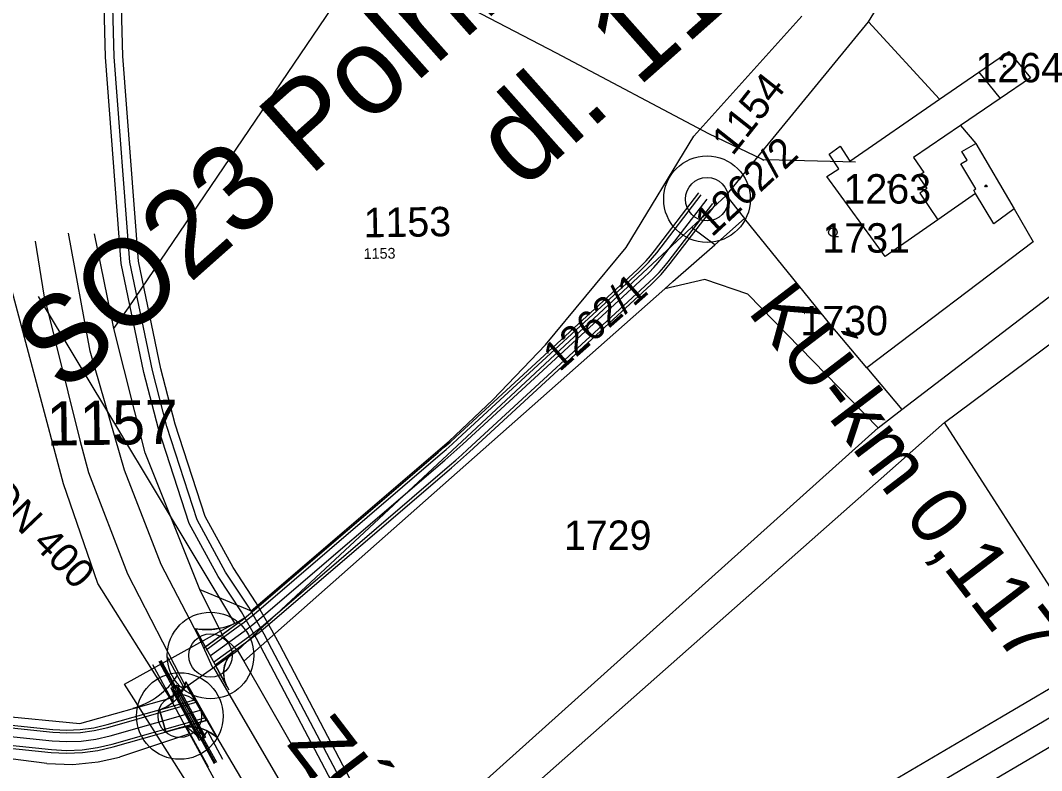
# Model space of a CAD drawing. Extents: x -510185 to -506993, y -1126306 to -1123642.
# Drawn here: x -508329.2 to -508152.3, y -1123958.7 to -1123828.7 of the extents above; entities that cross this region are included whole.
import ezdxf

# ---------------------------------------------------------------- set-up
doc = ezdxf.new("R2010")
doc.units = 0
for name, color, linetype in [('Net4gas', 7, 'Continuous'), ('návrh', 7, 'Continuous'), ('parcelni hranice', 7, 'Continuous'), ('popis cesty', 7, 'Continuous'), ('telefonica', 7, 'Continuous'), ('u_cesta23', 7, 'Continuous'), ('u_cesta45', 7, 'Continuous'), ('u_cesta50', 7, 'Continuous'), ('u_net4gas', 7, 'Continuous'), ('u_osa23', 7, 'Continuous'), ('u_osa50', 7, 'Continuous'), ('u_propustky', 7, 'Continuous'), ('u_Telefonica', 7, 'Continuous'), ('u_VaK', 7, 'Continuous'), ('u_ČEZ nadzemní nn', 7, 'Continuous'), ('u_ČEZ podzemní NN', 7, 'Continuous'), ('ˇ1', 7, 'Continuous'), ('ˇ2', 7, 'Continuous'), ('ˇ3', 7, 'Continuous'), ('ˇ4', 7, 'Continuous'), ('ˇ5', 7, 'Continuous')]:
    doc.layers.add(name, color=color, linetype=linetype)

msp = doc.modelspace()

# ---------------------------------------------------------------- linework, layer by layer
at = {"layer": 'Net4gas'}
for points in [[(-508209.34, -1123978.83), (-508159.28, -1123949.34), (-508132.58, -1123933.61), (-508126.96, -1123929.15), (-508083.48, -1123890.01), (-508045.36, -1123855.26), (-508012.03, -1123825.37), (-507981.75, -1123798.69), (-507943.8, -1123765.47), (-507913.54, -1123739.15), (-507890, -1123718.31)], [(-508198.87, -1123982.75), (-508154.86, -1123956.84), (-508127.64, -1123940.8), (-508121.34, -1123935.8), (-508077.64, -1123896.45), (-508039.53, -1123861.72), (-508006.25, -1123831.88), (-507976.01, -1123805.23), (-507938.08, -1123772.03), (-507907.8, -1123745.69), (-507890, -1123729.93)]]:
    msp.add_lwpolyline(points, dxfattribs=at)
at = {"layer": 'návrh'}
for centre, radius in [((-508210.29, -1123859.63), 7.5), ((-508210.29, -1123859.63), 3.75), ((-508296.29, -1123938.72), 7.5), ((-508296.29, -1123938.72), 3.75), ((-508301.61, -1123949.2), 7.5), ((-508301.61, -1123949.2), 3.75)]:
    msp.add_circle(centre, radius, dxfattribs=at)
at = {"layer": 'parcelni hranice'}
for p, q in [((-508182.33, -1123828.91), (-508153.43, -1123781.85)), ((-508207, -1123859.02), (-508182.33, -1123828.91)), ((-508182.33, -1123828.91), (-508170.02, -1123842.31)), ((-508163.21, -1123837.61), (-508158.04, -1123834.04)), ((-508158.04, -1123834.04), (-508154.26, -1123838.61)), ((-508170.02, -1123842.31), (-508163.21, -1123837.61)), ((-508163.21, -1123837.61), (-508159.52, -1123842.19)), ((-508154.26, -1123838.61), (-508159.52, -1123842.19)), ((-508185.53, -1123853.02), (-508170.02, -1123842.31)), ((-508159.52, -1123842.19), (-508166.38, -1123846.86)), ((-508166.38, -1123846.86), (-508163.75, -1123849.97)), ((-508189.11, -1123851.83), (-508187.21, -1123850.47)), ((-508187.21, -1123850.47), (-508185.53, -1123853.02)), ((-508163.75, -1123849.97), (-508157.1, -1123861.32)), ((-508187.46, -1123854.37), (-508189.11, -1123851.83)), ((-508189.52, -1123855.7), (-508187.46, -1123854.37)), ((-508179.44, -1123869.55), (-508189.52, -1123855.7)), ((-508212.95, -1123864.56), (-508207, -1123859.02)), ((-508207, -1123859.02), (-508206.25, -1123859.95)), ((-508206.25, -1123859.95), (-508203.81, -1123862.97)), ((-508163.76, -1123858.64), (-508170.3, -1123863.2)), ((-508160.63, -1123863.89), (-508163.76, -1123858.64)), ((-508176.54, -1123896.06), (-508130.51, -1123860.84)), ((-508157.1, -1123861.32), (-508160.63, -1123863.89)), ((-508157.1, -1123861.32), (-508153.77, -1123867.01)), ((-508208.96, -1123867.52), (-508203.81, -1123862.97)), ((-508188.77, -1123881.53), (-508203.81, -1123862.97)), ((-508170.3, -1123863.2), (-508179.44, -1123869.55)), ((-508291.61, -1123937.82), (-508212.95, -1123864.56)), ((-508208.96, -1123867.52), (-508212.95, -1123864.56)), ((-508153.77, -1123867.01), (-508182.6, -1123888.86)), ((-508216.2, -1123873.92), (-508208.96, -1123867.52)), ((-508210.68, -1123873.55), (-508217.6, -1123875.16)), ((-508217.6, -1123875.16), (-508216.2, -1123873.92)), ((-508203.22, -1123876.09), (-508210.68, -1123873.55)), ((-508217.6, -1123875.16), (-508290.54, -1123939.68)), ((-508203.22, -1123876.09), (-508180.63, -1123899.26)), ((-508182.6, -1123888.86), (-508188.77, -1123881.53)), ((-508169.14, -1123898.35), (-508149.98, -1123884.08)), ((-508182.6, -1123888.86), (-508176.54, -1123896.06)), ((-508180.63, -1123899.26), (-508176.54, -1123896.06)), ((-508169.14, -1123898.35), (-508265.66, -1123983.66)), ((-508106.47, -1123996.19), (-508169.14, -1123898.35)), ((-508268.66, -1123978.29), (-508180.63, -1123899.26)), ((-508295.77, -1123940.78), (-508291.61, -1123937.82)), ((-508291.61, -1123937.82), (-508290.54, -1123939.68)), ((-508290.54, -1123939.68), (-508278.92, -1123959.98)), ((-508300.37, -1123944.04), (-508295.77, -1123940.78)), ((-508295.77, -1123940.78), (-508268.93, -1123986.75)), ((-508303.29, -1123946.11), (-508300.37, -1123944.04)), ((-508318.91, -1123950.51), (-508303.29, -1123946.11)), ((-508299.93, -1123952.28), (-508303.29, -1123946.11)), ((-508354.46, -1123947.05), (-508318.91, -1123950.51)), ((-508324.63, -1123957.43), (-508353.26, -1123953.69)), ((-508299.93, -1123952.28), (-508312.04, -1123956.32)), ((-508299.93, -1123952.28), (-508284.75, -1123980.16)), ((-508324.63, -1123957.43), (-508320.16, -1123957.63)), ((-508320.16, -1123957.63), (-508315.75, -1123957.17)), ((-508315.75, -1123957.17), (-508312.04, -1123956.32))]:
    msp.add_line(p, q, dxfattribs=at)
at = {"layer": 'telefonica'}
for points in [[(-508202.41, -1124070), (-508212.32, -1124055.27), (-508225.01, -1124035.89), (-508229.3, -1124030.21), (-508235.63, -1124020.69), (-508238.99, -1124015.12), (-508245.74, -1124005.41), (-508247.67, -1124002.33), (-508255.76, -1123989.24), (-508263.22, -1123976.01), (-508271.46, -1123961.36), (-508284.31, -1123936.89), (-508285.67, -1123934.31), (-508288.37, -1123929.58), (-508292.39, -1123923.48), (-508297.22, -1123914.63), (-508302.41, -1123898.62), (-508304.9, -1123889.01), (-508308.77, -1123870.35), (-508311.46, -1123834.86), (-508312.01, -1123815.54)], [(-508204.89, -1124071.68), (-508214.82, -1124056.93), (-508227.47, -1124037.61), (-508231.74, -1124031.95), (-508238.17, -1124022.29), (-508241.51, -1124016.76), (-508248.24, -1124007.07), (-508250.21, -1124003.91), (-508258.34, -1123990.76), (-508265.84, -1123977.49), (-508274.1, -1123962.8), (-508286.97, -1123938.29), (-508288.31, -1123935.75), (-508290.93, -1123931.14), (-508294.97, -1123925.02), (-508299.98, -1123915.83), (-508305.29, -1123899.46), (-508307.82, -1123889.69), (-508311.75, -1123870.77), (-508314.46, -1123835.02), (-508314.97, -1123817.15)]]:
    msp.add_lwpolyline(points, dxfattribs=at)
at = {"layer": 'u_cesta23'}
msp.add_line((-508298.89, -1123934.07), (-508293.14, -1123944.68), dxfattribs=at)
for points in [[(-508297.32, -1123937.3), (-508291.5, -1123933.07), (-508290.77, -1123932.52), (-508290.06, -1123931.97), (-508289.35, -1123931.4), (-508288.66, -1123930.82), (-508256.83, -1123903.52), (-508255.8, -1123902.63), (-508254.79, -1123901.73), (-508253.78, -1123900.82), (-508222.36, -1123871.86), (-508221.56, -1123871.09), (-508220.81, -1123870.3), (-508220.09, -1123869.48), (-508219.4, -1123868.61), (-508211.68, -1123858.56)], [(-508297.03, -1123937.71), (-508291.21, -1123933.47), (-508290.47, -1123932.92), (-508289.75, -1123932.36), (-508289.04, -1123931.79), (-508288.33, -1123931.2), (-508256.5, -1123903.9), (-508255.47, -1123903.01), (-508254.45, -1123902.1), (-508253.45, -1123901.18), (-508222.02, -1123872.22), (-508221.21, -1123871.44), (-508220.44, -1123870.63), (-508219.71, -1123869.8), (-508219.01, -1123868.92), (-508211.28, -1123858.87)], [(-508295.75, -1123939.87), (-508289.73, -1123935.48), (-508288.96, -1123934.91), (-508288.2, -1123934.32), (-508287.45, -1123933.72), (-508286.71, -1123933.1), (-508254.87, -1123905.79), (-508253.82, -1123904.88), (-508252.78, -1123903.96), (-508251.76, -1123903.03), (-508220.31, -1123874.04), (-508219.44, -1123873.2), (-508218.6, -1123872.32), (-508217.79, -1123871.4), (-508217.04, -1123870.47), (-508209.3, -1123860.39)], [(-508295.51, -1123940.31), (-508289.43, -1123935.89), (-508288.65, -1123935.31), (-508287.89, -1123934.72), (-508287.13, -1123934.11), (-508286.39, -1123933.48), (-508254.54, -1123906.17), (-508253.49, -1123905.26), (-508252.45, -1123904.33), (-508251.42, -1123903.4), (-508219.96, -1123874.4), (-508219.08, -1123873.56), (-508218.23, -1123872.66), (-508217.41, -1123871.73), (-508216.65, -1123870.77), (-508208.9, -1123860.69)]]:
    msp.add_lwpolyline(points, dxfattribs=at)
for points in [[(-508298.89, -1123934.07), (-508297.19, -1123937.2), (-508290.41, -1123932.25), (-508291.47, -1123932.87), (-508292.85, -1123933.5), (-508294.17, -1123933.9), (-508295.76, -1123934.17), (-508296.89, -1123934.23), (-508298.04, -1123934.18)], [(-508293.47, -1123944.08), (-508295.51, -1123940.31), (-508292.2, -1123937.9), (-508292.8, -1123938.45), (-508293.43, -1123939.3), (-508293.92, -1123940.49), (-508294.08, -1123941.68), (-508293.92, -1123942.95)]]:
    msp.add_lwpolyline(points, close=True, dxfattribs=at)
for centre, radius, start, end in [((-508297.01, -1123922.22), 12, 260.9805, 303.9855), ((-508289.03, -1123941.78), 5, 129.2641, 207.4221)]:
    msp.add_arc(centre, radius, start, end, dxfattribs=at)
at = {"layer": 'u_cesta45'}
msp.add_arc((-508313.4, -1123934.87), 13.5, 285.9021, 327.4947, dxfattribs=at)
at = {"layer": 'u_cesta50'}
for p, q in [((-508302.68, -1123944.44), (-508305.21, -1123939.77)), ((-508302.42, -1123943.98), (-508304.81, -1123939.56)), ((-508300.89, -1123944.27), (-508303.76, -1123938.99)), ((-508302.76, -1123946.8), (-508306.26, -1123940.34)), ((-508300.55, -1123943.29), (-508295.01, -1123953.07)), ((-508302.76, -1123946.8), (-508302.68, -1123944.44)), ((-508300.89, -1123944.27), (-508302.42, -1123943.98)), ((-508305.13, -1123948.11), (-508304.03, -1123951.96)), ((-508296.66, -1123958.06), (-508300.48, -1123951.02)), ((-508300.48, -1123951.02), (-508298.02, -1123953.03)), ((-508297.54, -1123952.98), (-508296.82, -1123951.78)), ((-508294.15, -1123956.71), (-508296.82, -1123951.78)), ((-508295.6, -1123957.49), (-508298.02, -1123953.03)), ((-508295.21, -1123957.28), (-508297.54, -1123952.98))]:
    msp.add_line(p, q, dxfattribs=at)
for points in [[(-508304.91, -1123948.05), (-508298.85, -1123946.32), (-508300.55, -1123943.29), (-508300.73, -1123943.89), (-508301.08, -1123944.71), (-508301.67, -1123945.63), (-508302.15, -1123946.2), (-508302.67, -1123946.74), (-508303.3, -1123947.22), (-508304, -1123947.65), (-508304.56, -1123947.92)], [(-508305.13, -1123948.11), (-508299.08, -1123946.38), (-508297.04, -1123949.97), (-508304.03, -1123951.96)], [(-508302.12, -1123951.41), (-508300.66, -1123951.09), (-508300.03, -1123951.05), (-508298.95, -1123951.12), (-508297.99, -1123951.3), (-508296.7, -1123951.83), (-508295.58, -1123952.55), (-508295.01, -1123953.07), (-508296.82, -1123949.9)]]:
    msp.add_lwpolyline(points, close=True, dxfattribs=at)
for points in [[(-508344.04, -1123949.89), (-508323.62, -1123952.01), (-508321.19, -1123952.14), (-508318.8, -1123952.05), (-508316.42, -1123951.73), (-508314.05, -1123951.17), (-508298.6, -1123946.77)], [(-508343.98, -1123949.39), (-508323.58, -1123951.51), (-508321.19, -1123951.64), (-508318.84, -1123951.55), (-508316.51, -1123951.23), (-508314.18, -1123950.69), (-508298.85, -1123946.32)], [(-508344.43, -1123953.37), (-508323.9, -1123955.5), (-508321.22, -1123955.65), (-508318.49, -1123955.54), (-508315.79, -1123955.17), (-508313.17, -1123954.56), (-508296.84, -1123949.91)], [(-508344.38, -1123952.87), (-508323.86, -1123955), (-508321.22, -1123955.15), (-508318.54, -1123955.04), (-508315.88, -1123954.68), (-508313.3, -1123954.08), (-508297.1, -1123949.46)]]:
    msp.add_lwpolyline(points, dxfattribs=at)
for centre, radius, start, end in [((-508307.31, -1123941.47), 7, 290.0711, 344.9277), ((-508307.31, -1123941.47), 5.5, 327.3523, 332.878), ((-508299.92, -1123958.06), 7, 45.4608, 108.305), ((-508297.22, -1123958.47), 5.5, 93.3142, 98.3936)]:
    msp.add_arc(centre, radius, start, end, dxfattribs=at)
at = {"layer": 'u_net4gas'}
msp.add_lwpolyline([(-508251.72, -1124009.37), (-508251.34, -1124009.14), (-508211.3, -1123985.03), (-508157.07, -1123953.09), (-508130.11, -1123937.2), (-508124.15, -1123932.47), (-508080.56, -1123893.23), (-508042.45, -1123858.49), (-508009.14, -1123828.62), (-507978.88, -1123801.96), (-507940.94, -1123768.75), (-507910.72, -1123742.46)], dxfattribs=at)
at = {"layer": 'u_osa23'}
msp.add_lwpolyline([(-508296.29, -1123938.72), (-508290.47, -1123934.48), (-508289.71, -1123933.92), (-508288.97, -1123933.34), (-508288.24, -1123932.75), (-508287.52, -1123932.15), (-508255.68, -1123904.85), (-508254.65, -1123903.95), (-508253.62, -1123903.03), (-508252.6, -1123902.11), (-508221.16, -1123873.13), (-508220.32, -1123872.32), (-508219.52, -1123871.48), (-508218.75, -1123870.6), (-508218.02, -1123869.69), (-508210.29, -1123859.63)], dxfattribs=at)
at = {"layer": 'u_osa50'}
msp.add_lwpolyline([(-508344.21, -1123951.38), (-508323.74, -1123953.5), (-508321.2, -1123953.64), (-508318.67, -1123953.54), (-508316.15, -1123953.2), (-508313.68, -1123952.62), (-508297.85, -1123948.11)], dxfattribs=at)
at = {"layer": 'u_propustky'}
for p, q in [((-508302.61, -1123944.08), (-508305.01, -1123939.67)), ((-508303.18, -1123944.4), (-508302.06, -1123943.78)), ((-508303.18, -1123944.4), (-508298.25, -1123953.4)), ((-508298.34, -1123952.78), (-508302.68, -1123944.8)), ((-508297.71, -1123953.13), (-508302.61, -1123944.08)), ((-508298.24, -1123952.73), (-508302.59, -1123944.75)), ((-508297.73, -1123952.47), (-508302.08, -1123944.47)), ((-508302.06, -1123943.78), (-508297.15, -1123952.84)), ((-508297.63, -1123952.42), (-508301.99, -1123944.42)), ((-508298.25, -1123953.4), (-508297.15, -1123952.84)), ((-508295.41, -1123957.38), (-508297.71, -1123953.13))]:
    msp.add_line(p, q, dxfattribs=at)
for centre, major_axis, start_param, end_param in [((-508302.33, -1123944.63), (0.378, -0.69), 4.617178, 7.692002), ((-508302.33, -1123944.63), (0.378, -0.69), 4.832921, 7.639569), ((-508297.99, -1123952.58), (0.355, -0.702), 1.895216, 4.490849)]:
    msp.add_ellipse(centre, major_axis=major_axis, ratio=0.81635, start_param=start_param, end_param=end_param, dxfattribs=at)
for centre, major_axis, ratio in [((-508302.33, -1123944.61), (-0.286, 0.521), 0.66332), ((-508302.33, -1123944.61), (-0.209, 0.381), 0.659487), ((-508297.98, -1123952.6), (-0.268, 0.53), 0.66332), ((-508297.98, -1123952.6), (-0.196, 0.388), 0.659487)]:
    msp.add_ellipse(centre, major_axis=major_axis, ratio=ratio, dxfattribs=at)
at = {"layer": 'u_Telefonica'}
msp.add_line((-508286.99, -1123935.03), (-508289.65, -1123930.36), dxfattribs=at)
msp.add_line((-508286.99, -1123935.03), (-508289.65, -1123930.36), dxfattribs=at)
msp.add_lwpolyline([(-508203.65, -1124070.84), (-508213.57, -1124056.1), (-508226.24, -1124036.75), (-508230.52, -1124031.08), (-508236.9, -1124021.49), (-508240.25, -1124015.94), (-508246.99, -1124006.24), (-508248.94, -1124003.12), (-508257.05, -1123990), (-508264.53, -1123976.75), (-508272.78, -1123962.08), (-508285.64, -1123937.59), (-508286.99, -1123935.03), (-508289.65, -1123930.36), (-508293.68, -1123924.25), (-508298.6, -1123915.23), (-508303.85, -1123899.04), (-508306.36, -1123889.35), (-508310.26, -1123870.56), (-508312.96, -1123834.94), (-508313.51, -1123815.58)], dxfattribs=at)
msp.add_lwpolyline([(-508203.65, -1124070.84), (-508213.57, -1124056.1), (-508226.24, -1124036.75), (-508230.52, -1124031.08), (-508236.9, -1124021.49), (-508240.25, -1124015.94), (-508246.99, -1124006.24), (-508248.94, -1124003.12), (-508257.05, -1123990), (-508264.53, -1123976.75), (-508272.78, -1123962.08), (-508285.64, -1123937.59), (-508286.99, -1123935.03), (-508289.65, -1123930.36), (-508293.68, -1123924.25), (-508298.6, -1123915.23), (-508303.85, -1123899.04), (-508306.36, -1123889.35), (-508310.26, -1123870.56), (-508312.96, -1123834.94), (-508313.51, -1123815.58)], dxfattribs=at)
at = {"layer": 'u_VaK'}
msp.add_lwpolyline([(-508278.26, -1123995.47), (-508311.16, -1123943.7), (-508292.07, -1123933.12), (-508326.06, -1123876.52)], dxfattribs=at)
at = {"layer": 'u_ČEZ nadzemní nn'}
msp.add_line((-508200.71, -1123852.71), (-508200.46, -1123852.87), dxfattribs=at)
msp.add_lwpolyline([(-508322.11, -1123772.65), (-508322.11, -1123772.93), (-508316.85, -1123792.3), (-508289.83, -1123806.22), (-508263.72, -1123820.02), (-508236.43, -1123834.28), (-508210.01, -1123848.25), (-508200.71, -1123852.71)], dxfattribs=at)
at = {"layer": 'u_ČEZ podzemní NN'}
msp.add_lwpolyline([(-508200.46, -1123852.84), (-508199.96, -1123852.73), (-508184.56, -1123853.14)], dxfattribs=at)
at = {"layer": 'ˇ1'}
for points in [[(-508313.01, -1123882.06), (-508310.47, -1123878.48), (-508258.73, -1123802.02)], [(-508298.15, -1123927.28), (-508289.27, -1123930.98), (-508254.97, -1123901.59), (-508247.41, -1123894.4), (-508238.28, -1123884.89), (-508224.31, -1123868.03), (-508212.6, -1123848.71), (-508193.85, -1123827.93)], [(-508298.16, -1123927.28), (-508307.62, -1123903.58), (-508313.01, -1123882.06), (-508316.41, -1123865.65)], [(-508303.29, -1123946.11), (-508315.78, -1123926.26), (-508321.75, -1123908.96), (-508331.12, -1123873.87), (-508331.33, -1123868.9)], [(-508291.61, -1123937.82), (-508294.11, -1123935.41), (-508298.15, -1123927.28)]]:
    msp.add_lwpolyline(points, dxfattribs=at)
at = {"layer": 'ˇ3'}
msp.add_lwpolyline([(-508188.49, -1123866.1), (-508188.86, -1123866), (-508189.14, -1123865.73), (-508189.24, -1123865.35), (-508189.14, -1123864.98), (-508188.86, -1123864.7), (-508188.49, -1123864.6), (-508188.11, -1123864.7), (-508187.84, -1123864.98), (-508187.74, -1123865.35), (-508187.84, -1123865.73), (-508188.11, -1123866), (-508188.49, -1123866.1), (-508187.49, -1123866.1)], dxfattribs=at)
at = {"layer": 'ˇ4'}
for p, q in [((-508166.38, -1123846.86), (-508174.53, -1123852.4)), ((-508166.13, -1123851.39), (-508163.75, -1123849.97)), ((-508165.25, -1123852.87), (-508166.13, -1123851.39)), ((-508174.53, -1123852.4), (-508172.75, -1123855.01)), ((-508166.3, -1123853.49), (-508165.25, -1123852.87)), ((-508163.7, -1123857.85), (-508166.3, -1123853.49)), ((-508172.75, -1123855.01), (-508173.7, -1123855.66)), ((-508173.7, -1123855.66), (-508172.24, -1123857.81)), ((-508172.24, -1123857.81), (-508173.42, -1123858.61)), ((-508164.09, -1123858.08), (-508163.7, -1123857.85)), ((-508163.76, -1123858.64), (-508164.09, -1123858.08)), ((-508173.42, -1123858.61), (-508170.3, -1123863.2)), ((-508297.04, -1123949.67), (-508300.37, -1123944.04)), ((-508251.11, -1124027.5), (-508297.04, -1123949.67))]:
    msp.add_line(p, q, dxfattribs=at)
for points in [[(-508295.88, -1123940.86), (-508298.35, -1123935.39), (-508304.82, -1123922.96), (-508311.19, -1123906.6), (-508317.14, -1123886), (-508320.91, -1123865.51)], [(-508326.65, -1123866.89), (-508325.15, -1123876.27), (-508318.93, -1123901.39), (-508317.45, -1123907.01), (-508310.69, -1123924.58), (-508300.59, -1123944.2)]]:
    msp.add_lwpolyline(points, dxfattribs=at)
at = {"layer": 'ˇ5'}
for points in [[(-508158.66, -1123836.43), (-508158.58, -1123836.58), (-508158.66, -1123836.73), (-508158.84, -1123836.73), (-508158.92, -1123836.58), (-508158.84, -1123836.43)], [(-508158.66, -1123836.43), (-508158.58, -1123836.58), (-508158.66, -1123836.73), (-508158.84, -1123836.73), (-508158.92, -1123836.58), (-508158.84, -1123836.43)], [(-508178.66, -1123856.54), (-508178.58, -1123856.69), (-508178.66, -1123856.84), (-508178.84, -1123856.84), (-508178.92, -1123856.69), (-508178.84, -1123856.54)], [(-508161.87, -1123857.19), (-508161.79, -1123857.34), (-508161.87, -1123857.49), (-508162.05, -1123857.49), (-508162.14, -1123857.34), (-508162.05, -1123857.19)]]:
    msp.add_lwpolyline(points, close=True, dxfattribs=at)

# ---------------------------------------------------------------- texts
at = {"layer": 'popis cesty'}
for s, height, rotation, p in [('SO23 Polní cesta PC 23 ', 15, 41.6108, (-508321.63, -1123893.61)), ('dl. 117m', 15, 41.6108, (-508242.28, -1123858.17)), ('KÚ-km 0,117', 10, 307.4004, (-508203.4, -1123879.13)), ('propustek DN 400', 5, 313.77, (-508356.85, -1123888.59)), ('ZÚ-km 0,000 ', 10, 307.4004, (-508283.26, -1123954.05))]:
    msp.add_text(s, height=height, rotation=rotation, dxfattribs=at).set_placement(p)
at = {"layer": 'ˇ2'}
for s, p in [('1264', (-508163.8, -1123839.38)), ('1263', (-508186.65, -1123860.4)), ('1731', (-508190.3, -1123868.9)), ('1730', (-508194.12, -1123883.22)), ('1729', (-508235.08, -1123920.42))]:
    msp.add_text(s, height=5.1, dxfattribs=at).set_placement(p)
for s, height, rotation, p in [('1154', 5.1, 51.7224, (-508205.87, -1123852.29)), ('1262/2', 5.1, 42.7999, (-508209.45, -1123866.34)), ('1153', 5.1, 0.8295, (-508269.75, -1123866.26)), ('1153', 1.853, 0.8295, (-508269.75, -1123870)), ('1262/1', 5.1, 41.4248, (-508235.85, -1123889.68)), ('1157', 7.65, 0.8295, (-508324.64, -1123902.35))]:
    msp.add_text(s, height=height, rotation=rotation, dxfattribs=at).set_placement(p)

doc.saveas('drawing.dxf')
